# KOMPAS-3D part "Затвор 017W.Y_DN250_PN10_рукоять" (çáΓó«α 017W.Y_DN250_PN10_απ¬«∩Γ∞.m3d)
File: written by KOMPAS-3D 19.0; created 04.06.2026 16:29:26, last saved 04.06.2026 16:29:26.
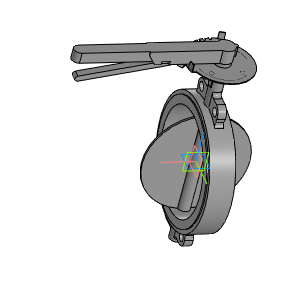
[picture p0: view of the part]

Document properties: Автор: Энергия; Полное имя файла: ..\..\..\3d для проектировщиков\017W разные\x.x Тип 017W.Y(S) Затвор дисковый поворотный межфланцевый\Затвор 017W.Y(S)_DN32-DN350_рукоять\Затвор 017W.Y_DN250_PN10_рукоять.a3d

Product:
- Part/product: Затвор 017W.Y_DN250_PN10_рукоять
    Масса: 23.5321

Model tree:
1. Операция без истории:1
